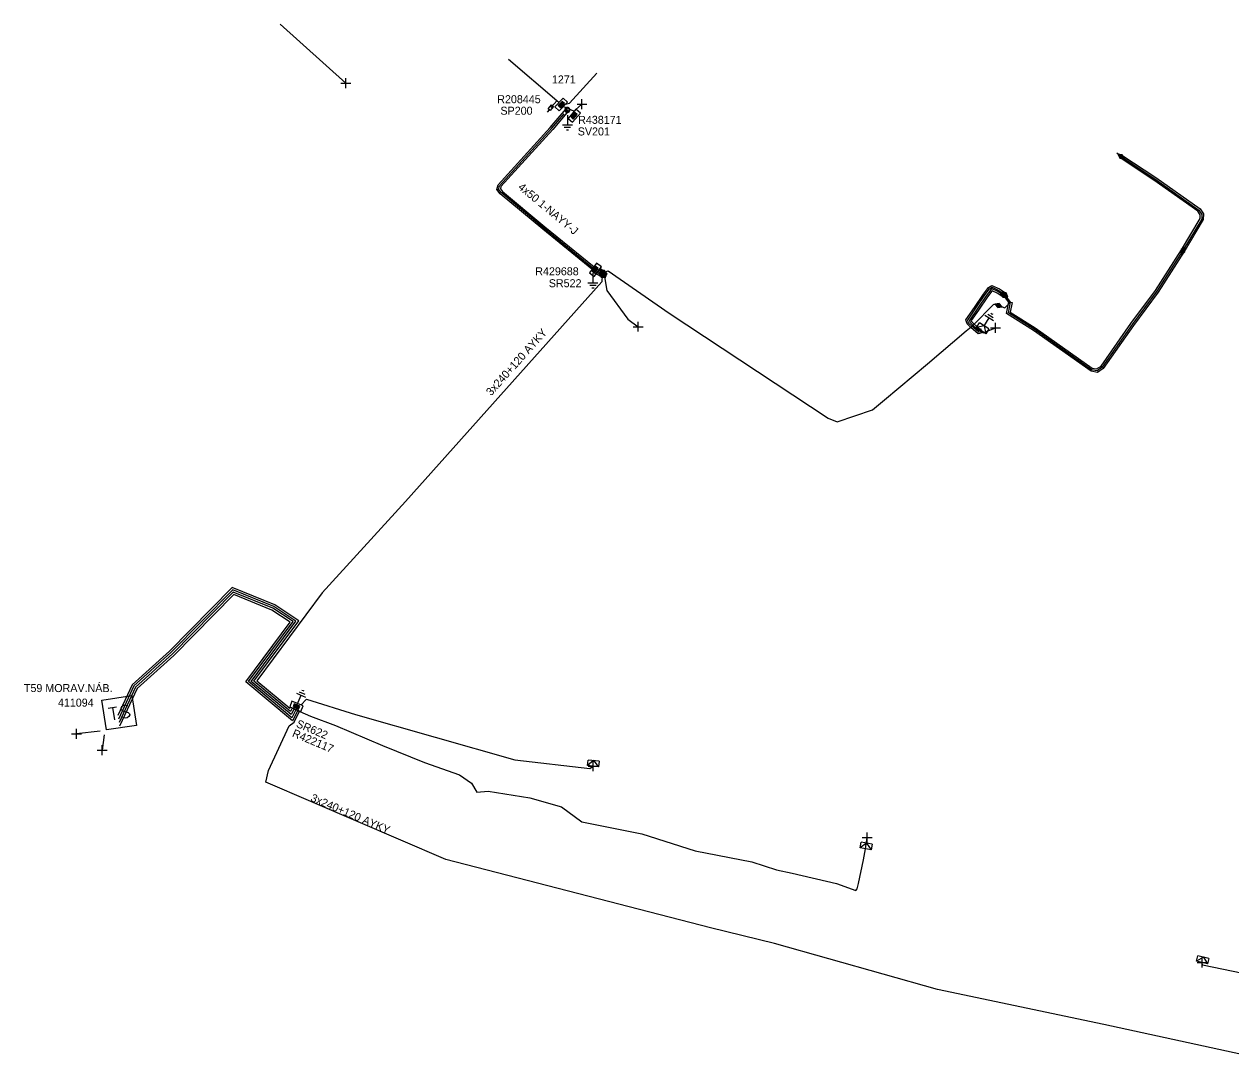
# Model space of a CAD drawing. Extents: x -540247 to -537390, y -1183890 to -1180355.
# Drawn here: x -538082.2 to -537931.4, y -1180514.9 to -1180384.4 of the extents above; entities that cross this region are included whole.
import ezdxf

# ---------------------------------------------------------------- set-up
doc = ezdxf.new("R2010")
doc.units = 0
for name, color, linetype in [('Vrstva 1', 7, 'Continuous'), ('Vrstva 13', 7, 'Continuous'), ('Vrstva 14', 7, 'Continuous'), ('Vrstva 15', 7, 'Continuous'), ('Vrstva 16', 7, 'Continuous'), ('Vrstva 19', 7, 'Continuous'), ('Vrstva 2', 7, 'Continuous'), ('Vrstva 20', 7, 'Continuous'), ('Vrstva 25', 7, 'Continuous'), ('Vrstva 26', 7, 'Continuous'), ('Vrstva 27', 7, 'Continuous'), ('Vrstva 28', 7, 'Continuous'), ('Vrstva 29', 7, 'Continuous'), ('Vrstva 30', 7, 'Continuous'), ('Vrstva 31', 7, 'Continuous'), ('Vrstva 34', 7, 'Continuous'), ('Vrstva 4', 7, 'Continuous'), ('Vrstva 5', 7, 'Continuous'), ('Vrstva 52', 7, 'Continuous'), ('Vrstva 54', 7, 'Continuous'), ('Vrstva 59', 7, 'Continuous'), ('Vrstva 6', 7, 'Continuous'), ('Vrstva 8', 7, 'Continuous'), ('Vrstva 9', 7, 'Continuous')]:
    doc.layers.add(name, color=color, linetype=linetype)

# ---------------------------------------------------------------- blocks, each defined once
blk = doc.blocks.new('NN440')
at = {"layer": 'Vrstva 2'}
for points in [[(0.63, 0), (0.63, 0.06), (0.62, 0.13), (0.6, 0.19), (0.58, 0.25), (0.55, 0.31), (0.51, 0.37), (0.47, 0.42), (0.42, 0.46), (0.37, 0.51), (0.32, 0.54), (0.26, 0.57), (0.2, 0.59), (0.13, 0.61), (0.07, 0.62), (0, 0.63), (-0.06, 0.62), (-0.13, 0.61), (-0.19, 0.59), (-0.26, 0.57), (-0.31, 0.54), (-0.37, 0.51), (-0.42, 0.46), (-0.47, 0.42), (-0.51, 0.37), (-0.54, 0.31), (-0.57, 0.25), (-0.6, 0.19), (-0.62, 0.13), (-0.63, 0.06), (-0.63, 0), (-0.63, -0.07), (-0.62, -0.14), (-0.6, -0.2), (-0.57, -0.26), (-0.54, -0.32), (-0.51, -0.37), (-0.47, -0.43), (-0.42, -0.47), (-0.37, -0.51), (-0.31, -0.55), (-0.26, -0.58), (-0.19, -0.6), (-0.13, -0.62), (-0.06, -0.63), (0, -0.63), (0.07, -0.63), (0.13, -0.62), (0.2, -0.6), (0.26, -0.58), (0.32, -0.55), (0.37, -0.51), (0.42, -0.47), (0.47, -0.43), (0.51, -0.37), (0.55, -0.32), (0.58, -0.26), (0.6, -0.2), (0.62, -0.14), (0.63, -0.07), (0.63, 0)], [(-0.63, 0), (0.63, 0)], [(-0.6, -0.18), (0.57, -0.18)], [(-0.51, -0.32), (0.5, -0.32)], [(-0.37, -0.47), (0.35, -0.47)]]:
    blk.add_lwpolyline(points, dxfattribs=at)
blk = doc.blocks.new('NN870')
at = {"layer": 'Vrstva 4'}
for points in [[(0, -0.25), (0.5, 0), (0, 0.25), (-0.5, 0), (0, -0.25)], [(0.37, 0), (0, 0.19), (-0.36, 0), (0, -0.19), (0.37, 0)], [(0.24, 0), (0, 0.12), (-0.25, 0), (0, -0.12), (0.24, 0)], [(0.12, 0), (0, 0.06), (-0.13, 0), (0, -0.06), (0.12, 0)]]:
    blk.add_lwpolyline(points, dxfattribs=at)
blk = doc.blocks.new('NN800')
at = {"layer": 'Vrstva 1'}
for points in [[(-0.44, 0.44), (0.44, -0.44)], [(-0.44, -0.44), (0.44, 0.44)]]:
    blk.add_lwpolyline(points, dxfattribs=at)
blk = doc.blocks.new('NN820')
at = {"layer": 'Vrstva 13'}
for points in [[(0, 0), (0, -1.05)], [(-0.16, -0.81), (0.16, -0.81)], [(-0.16, -1.47), (-0.16, -0.81)], [(0.16, -1.47), (-0.16, -1.47)], [(0, -1.05), (-0.06, -0.93)], [(0, -1.05), (0.06, -0.93)], [(0, -1.47), (0, -1.87)], [(0.16, -0.81), (0.16, -1.47)]]:
    blk.add_lwpolyline(points, dxfattribs=at)
blk = doc.blocks.new('NN620')
at = {"layer": 'Vrstva 8'}
for points in [[(0.75, 0), (-0.75, 0)], [(-0.75, 0), (-0.75, -0.75)], [(0.75, -0.75), (0.75, 0)], [(-0.75, -0.75), (0.75, -0.75)], [(0.37, -0.18), (-0.38, -0.18)], [(-0.38, -0.18), (-0.38, -0.56)], [(-0.38, -0.56), (0.37, -0.56)], [(0.32, -0.23), (-0.33, -0.23)], [(-0.33, -0.23), (-0.33, -0.51)], [(-0.33, -0.51), (0.32, -0.51)], [(0.27, -0.27), (-0.28, -0.27)], [(-0.28, -0.27), (-0.28, -0.46)], [(-0.28, -0.46), (0.27, -0.46)], [(0.23, -0.32), (-0.23, -0.32)], [(-0.23, -0.32), (-0.23, -0.42)], [(-0.23, -0.42), (0.23, -0.42)], [(-0.19, -0.37), (0.19, -0.37)], [(0.23, -0.42), (0.23, -0.32)], [(0.27, -0.46), (0.27, -0.27)], [(0.32, -0.51), (0.32, -0.23)], [(0.37, -0.56), (0.37, -0.18)]]:
    blk.add_lwpolyline(points, dxfattribs=at)
blk = doc.blocks.new('NN630')
at = {"layer": 'Vrstva 9'}
for points in [[(0, -0.7), (-0.7, 0)], [(-0.7, -0.7), (-0.7, 0), (0.7, 0), (0.7, -0.7)], [(-0.7, -0.7), (0.7, -0.7)], [(0, -0.7), (0.7, 0)]]:
    blk.add_lwpolyline(points, dxfattribs=at)
blk = doc.blocks.new('NN810')
at = {"layer": 'Vrstva 14'}
for points in [[(0, -0.64), (0, -1.89)], [(0.63, -1.89), (-0.62, -1.89)], [(0.39, -2.2), (-0.4, -2.2)], [(0, -2.52), (-0.12, -2.52)], [(0.14, -2.52), (0, -2.52)]]:
    blk.add_lwpolyline(points, dxfattribs=at)
blk = doc.blocks.new('NN640')
at = {"layer": 'Vrstva 6'}
for points in [[(-1.89, 1.89), (1.89, 1.89)], [(-1.89, -1.89), (-1.89, 1.89)], [(1.89, 1.89), (1.89, -1.89)], [(-1.26, 0.79), (-0.22, 0.79)], [(-0.73, 0.79), (-0.73, -0.79)], [(1.2, 0.66), (0.94, 0.79), (0.66, 0.79), (0.41, 0.66), (0.28, 0.47), (0.28, 0.41), (0.41, 0.22), (1.13, -0.16), (1.26, -0.32), (1.26, -0.47), (1.13, -0.66), (0.91, -0.79), (0.63, -0.79), (0.5, -0.73), (0.28, -0.6)], [(1.89, -1.89), (-1.89, -1.89)]]:
    blk.add_lwpolyline(points, dxfattribs=at)

msp = doc.modelspace()

# ---------------------------------------------------------------- linework, layer by layer
at = {"layer": 'Vrstva 20'}
for points in [[(-538014.49, -1180395.02), (-538014.19, -1180395.28), (-538016.17, -1180397.59), (-538022.64, -1180404.72), (-538022.71, -1180405.01), (-538022.45, -1180405.35), (-538017.14, -1180409.77), (-538011.01, -1180414.76), (-538011.27, -1180415.06), (-538017.4, -1180410.07), (-538022.75, -1180405.63), (-538023.15, -1180405.09), (-538023, -1180404.52), (-538016.47, -1180397.33)], [(-537945.04, -1180400.79), (-537940.81, -1180403.6), (-537935.28, -1180407.53), (-537934.86, -1180408.14), (-537934.87, -1180408.85), (-537937.24, -1180412.84), (-537937.58, -1180412.64), (-537935.27, -1180408.73), (-537935.26, -1180408.26), (-537935.57, -1180407.81), (-537941.03, -1180403.94), (-537945.26, -1180401.13)], [(-537937.58, -1180412.63), (-537937.24, -1180412.85), (-537940.51, -1180417.91), (-537943.6, -1180422.1), (-537947.37, -1180427.46), (-537948.1, -1180427.95), (-537948.9, -1180427.82), (-537956.1, -1180422.71), (-537959.45, -1180420.61), (-537959.16, -1180419.14), (-537958.76, -1180419.22), (-537959.01, -1180420.41), (-537955.88, -1180422.37), (-537948.74, -1180427.44), (-537948.2, -1180427.53), (-537947.65, -1180427.17), (-537943.92, -1180421.86), (-537940.84, -1180417.7)], [(-538010.26, -1180414.99), (-538009.7, -1180415.29), (-538010.07, -1180416), (-538010.61, -1180415.72), (-538010.74, -1180415.63)], [(-537961.84, -1180418.51), (-537962.95, -1180420.17), (-537963.88, -1180421.49), (-537963.85, -1180421.59), (-537963.54, -1180421.9), (-537962.85, -1180422.49), (-537962.72, -1180422.45), (-537962.56, -1180423.03), (-537962.99, -1180423.15), (-537963.94, -1180422.34), (-537964.39, -1180421.89), (-537964.53, -1180421.37), (-537963.45, -1180419.83), (-537962.33, -1180418.18), (-537961.72, -1180417.36), (-537961.28, -1180417.08), (-537960.34, -1180417.52), (-537959.58, -1180418.03), (-537959.92, -1180418.53), (-537960.64, -1180418.04), (-537961.24, -1180417.76), (-537961.3, -1180417.8)]]:
    msp.add_lwpolyline(points, close=True, dxfattribs=at)
at = {"layer": 'Vrstva 5'}
for points in [[(-538011.14, -1180414.91), (-538017.27, -1180409.92), (-538022.6, -1180405.49), (-538022.93, -1180405.05), (-538022.82, -1180404.62), (-538016.32, -1180397.46), (-538014.75, -1180395.63)], [(-537945.15, -1180400.96), (-537945.69, -1180400.56)], [(-537945.15, -1180400.96), (-537940.92, -1180403.77), (-537935.42, -1180407.67), (-537935.06, -1180408.2), (-537935.07, -1180408.79), (-537937.41, -1180412.74)], [(-537937.41, -1180412.74), (-537940.67, -1180417.8), (-537943.76, -1180421.98), (-537947.51, -1180427.31), (-537948.15, -1180427.74), (-537948.82, -1180427.63), (-537955.99, -1180422.54), (-537959.23, -1180420.51), (-537958.96, -1180419.18), (-537959.68, -1180418.2)], [(-538009.98, -1180415.82), (-538010.05, -1180416.64), (-538034.58, -1180444.08), (-538045, -1180455.49), (-538053.16, -1180466.49), (-538049, -1180469.94), (-538048.94, -1180469.83)], [(-538009.98, -1180415.82), (-538010.51, -1180415.54), (-538010.62, -1180415.47)], [(-538009.89, -1180415.64), (-538010.41, -1180415.37), (-538010.5, -1180415.31)], [(-538009.8, -1180415.46), (-538010.31, -1180415.2), (-538010.38, -1180415.15)], [(-538009.8, -1180415.46), (-538009.24, -1180415.27), (-538001.63, -1180420.55), (-537981.74, -1180433.69), (-537980.64, -1180434.13), (-537976.21, -1180432.62), (-537974.69, -1180431.38), (-537969.34, -1180426.87), (-537964.49, -1180422.78), (-537963.68, -1180422.1), (-537961.03, -1180419.41), (-537960.46, -1180419.6)], [(-537959.8, -1180418.35), (-537960.54, -1180417.86), (-537961.25, -1180417.53), (-537961.44, -1180417.65), (-537962, -1180418.4), (-537964.09, -1180421.45), (-537964.03, -1180421.69), (-537963.67, -1180422.05), (-537962.9, -1180422.71), (-537962.8, -1180422.68), (-537962.64, -1180422.74), (-537962.75, -1180422.87), (-537962.94, -1180422.93), (-537963.81, -1180422.19), (-537964.21, -1180421.79), (-537964.31, -1180421.41), (-537963.28, -1180419.94), (-537962.16, -1180418.28), (-537961.58, -1180417.51), (-537961.27, -1180417.31), (-537960.44, -1180417.7), (-537959.68, -1180418.2)], [(-537960.46, -1180419.6), (-537959.66, -1180419.87), (-537959.1, -1180419.32), (-537959.8, -1180418.35)], [(-538048.71, -1180469.93), (-538048.92, -1180470.33), (-538053.5, -1180466.53), (-538047.89, -1180458.99), (-538050.91, -1180457), (-538056.21, -1180454.83), (-538064.05, -1180462.78), (-538068.72, -1180467), (-538070.5, -1180470.83)], [(-538048.48, -1180470.02), (-538048.84, -1180470.73), (-538053.84, -1180466.57), (-538048.25, -1180459.05), (-538051.03, -1180457.22), (-538056.15, -1180455.12), (-538063.88, -1180462.96), (-538068.51, -1180467.15), (-538070.43, -1180471.28)], [(-538048.25, -1180470.12), (-538048.76, -1180471.12), (-538054.18, -1180466.61), (-538048.6, -1180459.11), (-538051.15, -1180457.44), (-538056.09, -1180455.42), (-538063.7, -1180463.14), (-538068.31, -1180467.31), (-538070.36, -1180471.72)], [(-538048.02, -1180470.22), (-538048.68, -1180471.51), (-538054.52, -1180466.65), (-538048.96, -1180459.18), (-538051.27, -1180457.66), (-538056.03, -1180455.71), (-538063.53, -1180463.32), (-538068.1, -1180467.46), (-538070.3, -1180472.17)], [(-537920.56, -1180504.4), (-537922.18, -1180513.5), (-537922.39, -1180514.88), (-537947.28, -1180509.47), (-537968.09, -1180505.09), (-537988.44, -1180499.35), (-537996.47, -1180497.39), (-538029.52, -1180488.84), (-538052, -1180479.18), (-538051.68, -1180477.71), (-538049.11, -1180472.13), (-538048.48, -1180471.68), (-538047.8, -1180470.31)], [(-538048.4, -1180470.03), (-538048.42, -1180470.06), (-538046.42, -1180470.94), (-538043.32, -1180472.1), (-538037.42, -1180474.57), (-538032.21, -1180476.72), (-538027.8, -1180478.27), (-538026.32, -1180479.28), (-538025.64, -1180480.42), (-538024.25, -1180480.31), (-538019.01, -1180481.11), (-538015.07, -1180482.24), (-538012.53, -1180484.13), (-538005.04, -1180485.62), (-537998.36, -1180487.76), (-537991.29, -1180489.14), (-537988.21, -1180490.12), (-537986.23, -1180490.53), (-537980.71, -1180491.82), (-537978.31, -1180492.73), (-537978.11, -1180492.52), (-537977.94, -1180491.85), (-537977.35, -1180488.88), (-537977.07, -1180487.49)]]:
    msp.add_lwpolyline(points, dxfattribs=at)
at = {"layer": 'Vrstva 52'}
for points in [[(-538014.83, -1180394.74), (-538013.58, -1180395.25)], [(-538014.56, -1180394.42), (-538014.09, -1180394.3)], [(-538009.89, -1180415.64), (-538009.73, -1180415.77), (-538009.41, -1180417.72), (-538006.79, -1180421.31), (-538005.49, -1180422.24)], [(-537962.64, -1180422.74), (-537962.38, -1180422.99)], [(-538047.66, -1180469.53), (-538046.92, -1180468.8), (-538040.81, -1180470.7), (-538020.91, -1180476.38), (-538011.55, -1180477.45), (-538011.13, -1180477.18)], [(-537920.99, -1180504.29), (-537921.28, -1180504.86), (-537934.95, -1180502.04), (-537935.03, -1180501.72)]]:
    msp.add_lwpolyline(points, dxfattribs=at)
at = {"layer": 'Vrstva 54'}
msp.add_lwpolyline([(-538015.37, -1180394.28), (-538015.66, -1180394.02), (-538021.7, -1180388.83)], dxfattribs=at)
at = {"layer": 'Vrstva 59'}
for points in [[(-538050.23, -1180384.43), (-538042.04, -1180391.82)], [(-538014.09, -1180394.3), (-538010.64, -1180390.54)], [(-538013.31, -1180395.12), (-538012.51, -1180394.42)], [(-537962.38, -1180422.99), (-537960.85, -1180422.38)], [(-538072.73, -1180472.79), (-538075.67, -1180473.14)], [(-538072.21, -1180473.25), (-538072.48, -1180475.17)], [(-537977.07, -1180487.49), (-537976.86, -1180486.09)]]:
    msp.add_lwpolyline(points, dxfattribs=at)

# ---------------------------------------------------------------- block references
at = {"layer": 'Vrstva 13', "xscale": 0.5, "yscale": 0.5, "rotation": -40.68429711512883}
msp.add_blockref('NN440', (-538014.34, -1180395.15), dxfattribs=at)
at = {"layer": 'Vrstva 15'}
for p, rotation in [((-538014.34, -1180395.15), 0.32552487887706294), ((-538011.14, -1180414.91), -0.11027483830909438), ((-537962.64, -1180422.74), 147.4707971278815), ((-538048.35, -1180470.05), 157.18267779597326)]:
    msp.add_blockref('NN810', p, dxfattribs=dict(at, rotation=rotation))
at = {"layer": 'Vrstva 16', "rotation": -40.6994305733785}
msp.add_blockref('NN820', (-538015.66, -1180394.02), dxfattribs=at)
at = {"layer": 'Vrstva 19'}
for p, rotation in [((-537945.15, -1180400.96), -33.59619172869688), ((-537937.41, -1180412.74), 59.35728603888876), ((-538009.98, -1180415.82), -27.385355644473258), ((-538009.89, -1180415.64), -27.43972775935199), ((-538009.8, -1180415.46), -27.49552772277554), ((-537959.8, -1180418.35), -33.01034999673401), ((-537959.68, -1180418.2), -39.49146669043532), ((-537960.46, -1180419.6), -18.283772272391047)]:
    msp.add_blockref('NN870', p, dxfattribs=dict(at, rotation=rotation))
at = {"layer": 'Vrstva 25', "rotation": 8.769061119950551}
msp.add_blockref('NN640', (-538070.35, -1180470.49), dxfattribs=at)
at = {"layer": 'Vrstva 28'}
for p, rotation in [((-538014.83, -1180394.74), -134.0949193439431), ((-538013.77, -1180395.64), 49.31600002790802), ((-538011.14, -1180414.91), 53.13690000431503), ((-538048.35, -1180470.05), 157.18267779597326)]:
    msp.add_blockref('NN620', p, dxfattribs=dict(at, rotation=rotation))
at = {"layer": 'Vrstva 31'}
for p, rotation in [((-537962.64, -1180422.74), 147.4430638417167), ((-538011.13, -1180477.18), 174.1482444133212), ((-537977.07, -1180487.49), 169.87764996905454), ((-537935.03, -1180501.72), 165.88479725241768)]:
    msp.add_blockref('NN630', p, dxfattribs=dict(at, rotation=rotation))
at = {"layer": 'Vrstva 34'}
for p, rotation in [((-538042.04, -1180391.82), 44.99999995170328), ((-538012.51, -1180394.42), 45.00000009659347), ((-538005.49, -1180422.24), 45), ((-537960.85, -1180422.38), 45), ((-538075.67, -1180473.14), 45), ((-538072.48, -1180475.17), 45), ((-538011.13, -1180477.18), 45), ((-537976.86, -1180486.09), 44.99999995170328), ((-537935.03, -1180501.72), 44.99999995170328)]:
    msp.add_blockref('NN800', p, dxfattribs=dict(at, rotation=rotation))

# ---------------------------------------------------------------- texts
at = {"layer": 'Vrstva 14'}
msp.add_text('1271', height=1, dxfattribs=at).set_placement((-538016.27, -1180391.84))
at = {"layer": 'Vrstva 26'}
msp.add_text('411094', height=1, dxfattribs=at).set_placement((-538078, -1180469.73))
at = {"layer": 'Vrstva 27'}
msp.add_text('T59 MORAV.NÁB.', height=1, dxfattribs=at).set_placement((-538082.25, -1180467.91))
at = {"layer": 'Vrstva 29'}
for s, p in [('R208445', (-538023.1, -1180394.31)), ('R438171', (-538012.99, -1180396.89)), ('R429688', (-538018.35, -1180415.82))]:
    msp.add_text(s, height=1, dxfattribs=at).set_placement(p)
msp.add_text('R422117', height=1, rotation=337.183, dxfattribs=at).set_placement((-538048.81, -1180473.43))
at = {"layer": 'Vrstva 30'}
for s, p in [('SP200', (-538022.7, -1180395.75)), ('SV201', (-538013.04, -1180398.34)), ('SR522', (-538016.66, -1180417.31))]:
    msp.add_text(s, height=1, dxfattribs=at).set_placement(p)
msp.add_text('SR622', height=1, rotation=337.183, dxfattribs=at).set_placement((-538048.31, -1180472.24))
at = {"layer": 'Vrstva 6'}
for s, rotation, p in [('4x50 1-NAYY-J', 320.269, (-538020.59, -1180404.94)), ('3x240+120 AYKY', 48.203, (-538023.86, -1180430.95)), ('3x240+120 AYKY', 336.746, (-538046.51, -1180481.49))]:
    msp.add_text(s, height=1, rotation=rotation, dxfattribs=at).set_placement(p)

doc.saveas('drawing.dxf')
